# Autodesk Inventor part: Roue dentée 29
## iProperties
Created: 2002-05
Part Number: Roue dentée 29
Material: Par défaut
Document SubType Name: Modélisation
Designer: Flavien MARTY
Control State: 0
Master: False
Checked Out: False
Shininess: 20.0
Length Units: 11269
Angle Units: 11279
Time Units: 11290
Mass Units: 11283
Length Display Precision: 3
Angle Display Precision: 2
Compacted: True
Density: 0.0
Volumn: 0.0
Area: 0.0
PropertySet Name: Model Information
Author: Flavien MARTY
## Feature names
1. Extrusion1
2. Extrusion2
3. Perçage1 [Hole]
4. Extrusion3
